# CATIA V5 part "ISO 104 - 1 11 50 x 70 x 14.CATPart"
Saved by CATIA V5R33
Part number: ISO 104 - 1 11 50 x 70 x 14
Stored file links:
  C:\Users\Ryzen5700u\Desktop\robot_cicloidale_singolo\Assieme_robot_cicloidale_singolo\ISO 104 - 1 11 50 x 70 x 14.CATPart

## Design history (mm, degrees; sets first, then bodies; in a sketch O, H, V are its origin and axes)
Body1 "Solid1" (main body)
  Solid1: solid without history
